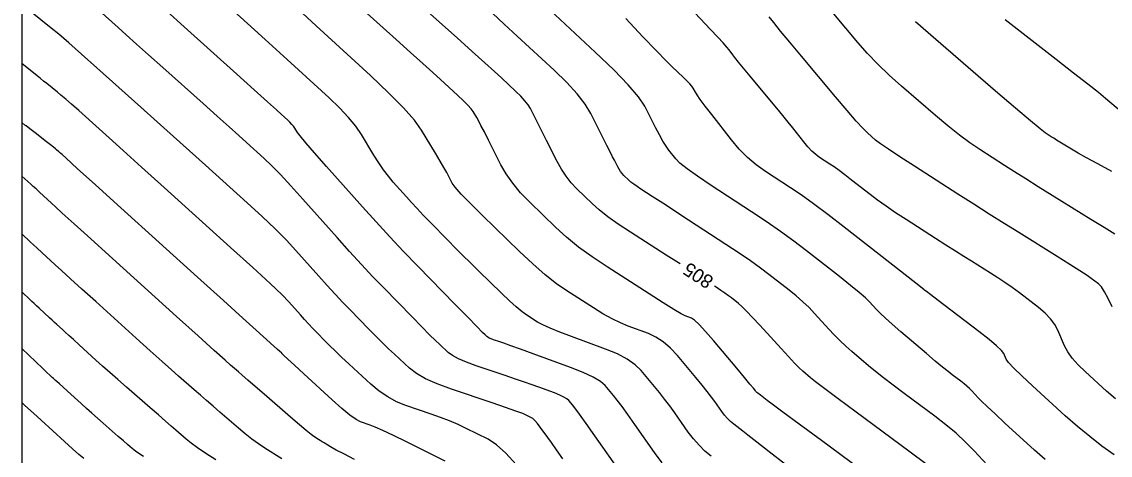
# Model space of a CAD drawing. Extents: x 2082232 to 2083549, y 592624 to 593832.
# Drawn here: x 2082231.8 to 2082287.6, y 593361.9 to 593384.1 of the extents above; entities that cross this region are included whole.
import ezdxf

# ---------------------------------------------------------------- set-up
doc = ezdxf.new("R2010")
doc.units = 0
for name, color, linetype in [('DT_X_Contour_Major', 7, 'Continuous'), ('DT_X_Contour_Minor', 7, 'Continuous'), ('DT_X_TIN_Hull', 7, 'Continuous')]:
    doc.layers.add(name, color=color, linetype=linetype)

msp = doc.modelspace()

# ---------------------------------------------------------------- linework, layer by layer
at = {"layer": 'DT_X_Contour_Major'}
for points in [[(2082265.562, 593371.67), (2082265.476, 593371.724), (2082264.846, 593372.128), (2082263.024, 593373.296), (2082262.389, 593373.715), (2082261.85, 593374.098), (2082261.407, 593374.445), (2082261.06, 593374.754), (2082260.262, 593375.531), (2082259.975, 593375.837), (2082259.712, 593376.171), (2082259.472, 593376.533), (2082259.257, 593376.924), (2082258.714, 593378.004), (2082258.525, 593378.381), (2082258.363, 593378.702), (2082258.23, 593378.966), (2082258.124, 593379.174), (2082257.88, 593379.654), (2082257.765, 593379.844), (2082257.603, 593380.054), (2082257.394, 593380.284), (2082257.137, 593380.533), (2082256.391, 593381.226), (2082256.038, 593381.549), (2082255.542, 593381.999), (2082254.902, 593382.577), (2082254.117, 593383.283), (2082251.833, 593385.333)], [(2082262.531, 593360.934), (2082261.185, 593362.846), (2082260.735, 593363.484), (2082260.393, 593363.963), (2082260.161, 593364.283), (2082260.039, 593364.444), (2082259.857, 593364.662), (2082259.759, 593364.747), (2082259.603, 593364.84), (2082259.388, 593364.94), (2082259.115, 593365.047), (2082258.309, 593365.342), (2082257.975, 593365.463), (2082257.577, 593365.603), (2082257.116, 593365.763), (2082256.592, 593365.942), (2082255.107, 593366.447), (2082254.6, 593366.632), (2082254.191, 593366.807), (2082253.88, 593366.972), (2082253.667, 593367.129), (2082253.23, 593367.533), (2082253.018, 593367.735), (2082252.712, 593368.039), (2082252.311, 593368.444), (2082251.814, 593368.951), (2082250.364, 593370.438), (2082249.806, 593371.018), (2082249.22, 593371.644), (2082248.605, 593372.314), (2082247.962, 593373.03), (2082246.21, 593375.001), (2082245.593, 593375.685), (2082245.055, 593376.262), (2082244.597, 593376.73), (2082244.219, 593377.089), (2082243.317, 593377.904), (2082242.924, 593378.258), (2082242.422, 593378.71), (2082241.81, 593379.258), (2082241.089, 593379.904), (2082239.019, 593381.755), (2082238.295, 593382.404), (2082237.672, 593382.962), (2082237.151, 593383.429), (2082236.733, 593383.805), (2082235.753, 593384.687)], [(2082287.724, 593369.463), (2082287.525, 593369.901), (2082287.342, 593370.244), (2082287.176, 593370.493), (2082287.027, 593370.647), (2082286.653, 593370.933), (2082286.438, 593371.083), (2082286.074, 593371.321), (2082285.562, 593371.647), (2082284.902, 593372.06), (2082282.942, 593373.278), (2082282.195, 593373.744), (2082281.423, 593374.23), (2082280.626, 593374.736), (2082279.804, 593375.261), (2082277.58, 593376.688), (2082276.831, 593377.174), (2082276.25, 593377.56), (2082275.838, 593377.846), (2082275.594, 593378.033), (2082275.17, 593378.399), (2082274.948, 593378.618), (2082274.602, 593378.998), (2082274.131, 593379.541), (2082273.536, 593380.245), (2082271.782, 593382.34), (2082271.185, 593383.055), (2082270.713, 593383.63), (2082270.363, 593384.065), (2082270.137, 593384.36)], [(2082245.123, 593361.668), (2082244.259, 593362.213), (2082243.932, 593362.431), (2082243.596, 593362.675), (2082243.253, 593362.944), (2082242.902, 593363.239), (2082241.955, 593364.062), (2082241.607, 593364.365), (2082241.271, 593364.657), (2082240.948, 593364.938), (2082240.638, 593365.209), (2082239.828, 593365.917), (2082239.465, 593366.237), (2082238.983, 593366.668), (2082238.382, 593367.207), (2082237.662, 593367.857), (2082235.584, 593369.736), (2082234.87, 593370.383), (2082234.285, 593370.913), (2082233.831, 593371.327), (2082233.506, 593371.625), (2082232.814, 593372.265), (2082232.578, 593372.483), (2082232.387, 593372.66), (2082232.242, 593372.794), (2082231.787, 593373.214)], [(2082278.233, 593361.362), (2082277.298, 593362.067), (2082274.587, 593364.067), (2082273.679, 593364.739), (2082272.988, 593365.256), (2082272.513, 593365.618), (2082272.255, 593365.824), (2082271.855, 593366.167), (2082271.673, 593366.335), (2082271.426, 593366.584), (2082271.115, 593366.914), (2082270.74, 593367.323), (2082269.652, 593368.522), (2082269.278, 593368.929), (2082268.971, 593369.251), (2082268.732, 593369.486), (2082268.561, 593369.637), (2082268.194, 593369.924), (2082268.041, 593370.039), (2082267.86, 593370.169), (2082267.648, 593370.313), (2082267.407, 593370.473), (2082267.324, 593370.527)]]:
    msp.add_lwpolyline(points, dxfattribs=at)
at = {"layer": 'DT_X_Contour_Minor'}
for points in [[(2082284.287, 593361.63), (2082283.747, 593362.114), (2082282.23, 593363.502), (2082281.718, 593363.973), (2082281.318, 593364.347), (2082281.031, 593364.622), (2082280.857, 593364.8), (2082280.541, 593365.143), (2082280.417, 593365.271), (2082280.279, 593365.398), (2082280.129, 593365.524), (2082279.967, 593365.65), (2082279.516, 593365.982), (2082279.307, 593366.144), (2082279.018, 593366.379), (2082278.648, 593366.688), (2082278.199, 593367.071), (2082276.894, 593368.191), (2082276.449, 593368.577), (2082276.092, 593368.896), (2082275.823, 593369.148), (2082275.642, 593369.332), (2082275.278, 593369.733), (2082275.079, 593369.927), (2082274.756, 593370.207), (2082274.309, 593370.573), (2082273.737, 593371.026), (2082272.046, 593372.349), (2082271.394, 593372.846), (2082270.706, 593373.346), (2082269.983, 593373.849), (2082269.224, 593374.355), (2082267.154, 593375.707), (2082266.458, 593376.172), (2082265.923, 593376.553), (2082265.549, 593376.849), (2082265.336, 593377.062), (2082264.982, 593377.517), (2082264.84, 593377.718), (2082264.679, 593377.977), (2082264.499, 593378.297), (2082264.301, 593378.676), (2082263.747, 593379.765), (2082263.433, 593380.246), (2082262.905, 593380.87), (2082262.164, 593381.638), (2082261.21, 593382.55), (2082258.38, 593385.173)], [(2082259.553, 593361.66), (2082259.218, 593362.135), (2082258.957, 593362.501), (2082258.773, 593362.758), (2082258.381, 593363.299), (2082258.241, 593363.482), (2082258.115, 593363.626), (2082258.003, 593363.73), (2082257.906, 593363.795), (2082257.663, 593363.914), (2082257.485, 593363.987), (2082257.135, 593364.115), (2082256.611, 593364.298), (2082255.915, 593364.537), (2082253.827, 593365.247), (2082253.105, 593365.514), (2082252.507, 593365.781), (2082252.032, 593366.049), (2082251.68, 593366.317), (2082250.906, 593367.033), (2082250.607, 593367.315), (2082250.289, 593367.622), (2082249.953, 593367.956), (2082249.599, 593368.316), (2082248.629, 593369.31), (2082248.256, 593369.698), (2082247.864, 593370.116), (2082247.453, 593370.564), (2082247.023, 593371.043), (2082245.851, 593372.361), (2082245.366, 593372.884), (2082244.789, 593373.466), (2082244.12, 593374.107), (2082243.359, 593374.806), (2082241.208, 593376.749), (2082240.396, 593377.482), (2082239.574, 593378.222), (2082238.741, 593378.969), (2082237.899, 593379.724), (2082235.637, 593381.747), (2082234.855, 593382.444), (2082234.204, 593383.015), (2082233.685, 593383.461), (2082233.297, 593383.783), (2082231.787, 593384.998)], [(2082264.65, 593361.466), (2082264.256, 593361.988), (2082263.236, 593363.436), (2082262.882, 593363.935), (2082262.582, 593364.348), (2082262.336, 593364.673), (2082262.146, 593364.912), (2082261.712, 593365.431), (2082261.479, 593365.635), (2082261.107, 593365.856), (2082260.595, 593366.094), (2082259.943, 593366.349), (2082258.019, 593367.054), (2082257.372, 593367.291), (2082256.873, 593367.472), (2082256.523, 593367.598), (2082256.322, 593367.669), (2082255.983, 593367.784), (2082255.867, 593367.827), (2082255.773, 593367.867), (2082255.702, 593367.905), (2082255.653, 593367.94), (2082255.553, 593368.033), (2082255.43, 593368.156), (2082255.135, 593368.456), (2082254.668, 593368.933), (2082254.03, 593369.587), (2082252.099, 593371.566), (2082251.379, 593372.313), (2082250.667, 593373.069), (2082249.963, 593373.833), (2082249.267, 593374.607), (2082247.42, 593376.683), (2082246.808, 593377.375), (2082246.356, 593377.894), (2082246.063, 593378.241), (2082245.93, 593378.415), (2082245.79, 593378.647), (2082245.728, 593378.738), (2082245.647, 593378.837), (2082245.548, 593378.943), (2082245.43, 593379.056), (2082245.091, 593379.368), (2082244.853, 593379.583), (2082244.395, 593379.997), (2082243.717, 593380.609), (2082242.818, 593381.419), (2082240.127, 593383.842), (2082239.22, 593384.666)], [(2082267.148, 593361.8), (2082266.832, 593362.067), (2082266.532, 593362.362), (2082266.248, 593362.687), (2082265.98, 593363.042), (2082265.288, 593364.025), (2082265.028, 593364.387), (2082264.77, 593364.733), (2082264.511, 593365.064), (2082264.254, 593365.379), (2082263.567, 593366.201), (2082263.259, 593366.5), (2082262.852, 593366.783), (2082262.345, 593367.049), (2082261.738, 593367.298), (2082259.987, 593367.939), (2082259.386, 593368.166), (2082258.897, 593368.367), (2082258.519, 593368.542), (2082258.253, 593368.69), (2082257.692, 593369.049), (2082257.453, 593369.221), (2082257.158, 593369.464), (2082256.806, 593369.781), (2082256.397, 593370.17), (2082255.233, 593371.305), (2082254.807, 593371.722), (2082254.402, 593372.123), (2082254.02, 593372.507), (2082253.659, 593372.874), (2082252.726, 593373.831), (2082252.388, 593374.18), (2082252.074, 593374.511), (2082251.785, 593374.823), (2082251.52, 593375.117), (2082250.845, 593375.876), (2082250.594, 593376.175), (2082250.345, 593376.503), (2082250.098, 593376.861), (2082249.855, 593377.248), (2082249.209, 593378.319), (2082248.923, 593378.738), (2082248.552, 593379.191), (2082248.096, 593379.678), (2082247.553, 593380.198), (2082245.992, 593381.632), (2082245.411, 593382.164), (2082244.842, 593382.684), (2082244.282, 593383.191), (2082243.734, 593383.686), (2082242.285, 593384.991)], [(2082270.969, 593361.375), (2082270.138, 593362.023), (2082269.497, 593362.525), (2082269.043, 593362.879), (2082268.778, 593363.086), (2082268.321, 593363.44), (2082268.155, 593363.581), (2082267.996, 593363.737), (2082267.846, 593363.909), (2082267.705, 593364.096), (2082267.339, 593364.615), (2082267.175, 593364.838), (2082266.958, 593365.118), (2082266.686, 593365.454), (2082266.361, 593365.847), (2082265.422, 593366.97), (2082265.065, 593367.356), (2082264.7, 593367.673), (2082264.325, 593367.92), (2082263.941, 593368.097), (2082262.906, 593368.476), (2082262.503, 593368.641), (2082262.069, 593368.852), (2082261.605, 593369.11), (2082261.111, 593369.413), (2082259.752, 593370.284), (2082259.218, 593370.655), (2082258.634, 593371.118), (2082258.001, 593371.671), (2082257.318, 593372.316), (2082255.431, 593374.155), (2082254.803, 593374.775), (2082254.334, 593375.259), (2082254.025, 593375.605), (2082253.875, 593375.814), (2082253.687, 593376.188), (2082253.592, 593376.366), (2082253.447, 593376.62), (2082253.254, 593376.949), (2082253.011, 593377.355), (2082252.298, 593378.537), (2082251.934, 593379.045), (2082251.375, 593379.681), (2082250.623, 593380.447), (2082249.676, 593381.341), (2082246.892, 593383.897), (2082245.969, 593384.745)], [(2082276.26, 593360.057), (2082272.814, 593362.6), (2082271.671, 593363.444), (2082270.826, 593364.068), (2082270.281, 593364.473), (2082270.034, 593364.659), (2082269.686, 593364.931), (2082269.618, 593364.984), (2082269.571, 593365.021), (2082269.543, 593365.043), (2082269.494, 593365.08), (2082269.477, 593365.095), (2082269.46, 593365.112), (2082269.444, 593365.13), (2082269.429, 593365.15), (2082269.391, 593365.204), (2082269.322, 593365.289), (2082269.146, 593365.502), (2082268.861, 593365.844), (2082268.469, 593366.314), (2082267.277, 593367.739), (2082266.871, 593368.212), (2082266.547, 593368.563), (2082266.305, 593368.79), (2082266.144, 593368.896), (2082265.825, 593369.013), (2082265.619, 593369.116), (2082265.241, 593369.337), (2082264.691, 593369.678), (2082263.968, 593370.136), (2082261.812, 593371.518), (2082261.042, 593372.032), (2082260.348, 593372.54), (2082259.73, 593373.041), (2082259.189, 593373.535), (2082257.846, 593374.843), (2082257.376, 593375.331), (2082256.973, 593375.814), (2082256.637, 593376.292), (2082256.367, 593376.765), (2082255.736, 593378.021), (2082255.52, 593378.447), (2082255.346, 593378.784), (2082255.215, 593379.032), (2082255.125, 593379.191), (2082254.941, 593379.496), (2082254.839, 593379.633), (2082254.673, 593379.818), (2082254.441, 593380.05), (2082254.144, 593380.33), (2082253.265, 593381.137), (2082252.875, 593381.492), (2082252.366, 593381.954), (2082251.738, 593382.52), (2082250.99, 593383.193), (2082248.835, 593385.126)], [(2082287.902, 593364.742), (2082287.446, 593365.136), (2082286.359, 593366.131), (2082285.986, 593366.495), (2082285.683, 593366.84), (2082285.45, 593367.167), (2082285.287, 593367.475), (2082284.946, 593368.272), (2082284.788, 593368.568), (2082284.57, 593368.86), (2082284.291, 593369.148), (2082283.952, 593369.431), (2082282.966, 593370.181), (2082282.597, 593370.455), (2082282.229, 593370.716), (2082281.862, 593370.964), (2082281.495, 593371.199), (2082280.518, 593371.806), (2082280.127, 593372.05), (2082279.686, 593372.328), (2082279.197, 593372.64), (2082278.658, 593372.985), (2082277.154, 593373.949), (2082276.616, 593374.301), (2082276.13, 593374.632), (2082275.694, 593374.943), (2082275.31, 593375.233), (2082274.353, 593375.981), (2082274.015, 593376.243), (2082273.717, 593376.466), (2082273.46, 593376.652), (2082273.243, 593376.799), (2082272.718, 593377.142), (2082272.519, 593377.288), (2082272.317, 593377.47), (2082272.112, 593377.687), (2082271.903, 593377.94), (2082271.342, 593378.662), (2082271.111, 593378.955), (2082270.837, 593379.293), (2082270.522, 593379.677), (2082270.165, 593380.105), (2082269.158, 593381.308), (2082268.819, 593381.715), (2082268.556, 593382.033), (2082268.371, 593382.262), (2082268.262, 593382.403), (2082268.074, 593382.659), (2082267.962, 593382.797), (2082267.767, 593383.017), (2082267.49, 593383.319), (2082267.13, 593383.703), (2082266.06, 593384.838)], [(2082281.754, 593360.878), (2082280.648, 593362.081), (2082280.211, 593362.53), (2082279.729, 593362.977), (2082279.203, 593363.419), (2082278.632, 593363.858), (2082277.052, 593365.024), (2082276.493, 593365.441), (2082276.003, 593365.818), (2082275.581, 593366.153), (2082275.227, 593366.448), (2082274.375, 593367.179), (2082274.061, 593367.456), (2082273.759, 593367.74), (2082273.469, 593368.031), (2082273.191, 593368.328), (2082272.465, 593369.128), (2082272.178, 593369.428), (2082271.864, 593369.729), (2082271.52, 593370.03), (2082271.149, 593370.331), (2082270.12, 593371.136), (2082269.692, 593371.459), (2082269.182, 593371.823), (2082268.589, 593372.229), (2082267.913, 593372.677), (2082265.999, 593373.927), (2082265.344, 593374.354), (2082264.814, 593374.699), (2082264.409, 593374.962), (2082264.13, 593375.142), (2082263.553, 593375.512), (2082263.352, 593375.644), (2082263.181, 593375.766), (2082263.041, 593375.875), (2082262.931, 593375.974), (2082262.678, 593376.22), (2082262.587, 593376.317), (2082262.504, 593376.422), (2082262.428, 593376.537), (2082262.36, 593376.661), (2082262.188, 593377.003), (2082262.102, 593377.173), (2082261.975, 593377.424), (2082261.806, 593377.757), (2082261.595, 593378.171), (2082260.978, 593379.387), (2082260.687, 593379.868), (2082260.276, 593380.399), (2082259.746, 593380.981), (2082259.096, 593381.613), (2082257.205, 593383.367), (2082256.532, 593383.989), (2082255.933, 593384.539)], [(2082287.834, 593361.878), (2082287.204, 593362.323), (2082286.575, 593362.805), (2082285.946, 593363.323), (2082285.319, 593363.879), (2082283.647, 593365.409), (2082283.092, 593365.925), (2082282.682, 593366.326), (2082282.417, 593366.611), (2082282.297, 593366.781), (2082282.169, 593367.08), (2082282.053, 593367.235), (2082281.801, 593367.474), (2082281.413, 593367.797), (2082280.89, 593368.205), (2082278.795, 593369.799), (2082278.423, 593370.082), (2082278.198, 593370.254), (2082278.119, 593370.314), (2082278.101, 593370.33), (2082278.095, 593370.335), (2082278.093, 593370.336), (2082278.091, 593370.339), (2082277.98, 593370.426), (2082277.649, 593370.685), (2082276.325, 593371.721), (2082273.972, 593373.561), (2082273.139, 593374.205), (2082272.405, 593374.755), (2082271.77, 593375.213), (2082271.234, 593375.577), (2082269.936, 593376.424), (2082269.463, 593376.764), (2082269.016, 593377.145), (2082268.596, 593377.57), (2082268.202, 593378.038), (2082267.188, 593379.341), (2082266.851, 593379.779), (2082266.597, 593380.115), (2082266.429, 593380.35), (2082266.345, 593380.483), (2082266.233, 593380.702), (2082266.17, 593380.799), (2082266.064, 593380.924), (2082265.915, 593381.079), (2082265.723, 593381.262), (2082265.154, 593381.79), (2082264.845, 593382.093), (2082264.345, 593382.607), (2082263.654, 593383.332), (2082262.772, 593384.268)], [(2082287.871, 593373.203), (2082287.32, 593373.538), (2082286.64, 593373.958), (2082284.651, 593375.194), (2082283.939, 593375.638), (2082283.294, 593376.042), (2082282.716, 593376.407), (2082282.206, 593376.733), (2082280.934, 593377.549), (2082280.434, 593377.888), (2082279.891, 593378.291), (2082279.302, 593378.759), (2082278.67, 593379.292), (2082276.923, 593380.798), (2082276.292, 593381.362), (2082275.709, 593381.922), (2082275.175, 593382.479), (2082274.688, 593383.033), (2082273.454, 593384.506)], [(2082287.718, 593376.411), (2082286.986, 593376.803), (2082286.41, 593377.116), (2082285.989, 593377.351), (2082285.723, 593377.507), (2082285.223, 593377.818), (2082285.043, 593377.929), (2082284.881, 593378.031), (2082284.736, 593378.123), (2082284.607, 593378.205), (2082284.287, 593378.411), (2082284.038, 593378.602), (2082283.531, 593379.022), (2082282.767, 593379.672), (2082281.745, 593380.55), (2082278.677, 593383.197), (2082277.636, 593384.106)], [(2082288.161, 593379.514), (2082287.394, 593380.161), (2082287.019, 593380.469), (2082286.472, 593380.907), (2082285.751, 593381.474), (2082284.857, 593382.171), (2082282.242, 593384.202)], [(2082257.151, 593361.373), (2082256.627, 593361.958), (2082256.145, 593362.392), (2082255.707, 593362.674), (2082254.593, 593363.223), (2082254.168, 593363.424), (2082253.725, 593363.615), (2082253.265, 593363.795), (2082252.789, 593363.965), (2082251.496, 593364.405), (2082251.02, 593364.597), (2082250.561, 593364.845), (2082250.119, 593365.148), (2082249.694, 593365.506), (2082248.583, 593366.533), (2082248.195, 593366.894), (2082247.866, 593367.205), (2082247.595, 593367.468), (2082247.383, 593367.68), (2082246.894, 593368.182), (2082246.705, 593368.377), (2082246.508, 593368.588), (2082246.3, 593368.815), (2082246.084, 593369.056), (2082245.493, 593369.721), (2082245.139, 593370.083), (2082244.523, 593370.67), (2082243.643, 593371.484), (2082242.499, 593372.523), (2082239.099, 593375.594), (2082237.934, 593376.646), (2082236.989, 593377.499), (2082236.264, 593378.151), (2082235.76, 593378.604), (2082234.707, 593379.545), (2082234.343, 593379.869), (2082234.04, 593380.135), (2082233.799, 593380.343), (2082233.619, 593380.492), (2082233.067, 593380.936), (2082232.91, 593381.063), (2082232.748, 593381.193), (2082232.58, 593381.328), (2082231.787, 593381.966)], [(2082253.508, 593361.553), (2082251.524, 593362.532), (2082250.85, 593362.861), (2082250.315, 593363.115), (2082249.919, 593363.292), (2082249.663, 593363.393), (2082249.166, 593363.562), (2082248.935, 593363.681), (2082248.615, 593363.909), (2082248.206, 593364.246), (2082247.707, 593364.694), (2082246.259, 593366.033), (2082245.784, 593366.473), (2082245.443, 593366.789), (2082245.238, 593366.979), (2082245.167, 593367.045), (2082245.159, 593367.054), (2082245.155, 593367.057), (2082245.152, 593367.061), (2082245.148, 593367.065), (2082245.144, 593367.069), (2082245.134, 593367.081), (2082245.105, 593367.107), (2082245.026, 593367.179), (2082244.897, 593367.296), (2082244.718, 593367.458), (2082244.174, 593367.949), (2082243.811, 593368.278), (2082243.129, 593368.894), (2082242.128, 593369.799), (2082240.808, 593370.993), (2082236.864, 593374.559), (2082235.567, 593375.733), (2082234.633, 593376.577), (2082234.062, 593377.094), (2082233.854, 593377.282), (2082233.785, 593377.346), (2082233.758, 593377.371), (2082233.729, 593377.397), (2082233.698, 593377.424), (2082233.666, 593377.453), (2082233.576, 593377.531), (2082233.519, 593377.579), (2082233.414, 593377.662), (2082233.262, 593377.782), (2082233.062, 593377.937), (2082232.467, 593378.4), (2082232.267, 593378.556), (2082232.114, 593378.675), (2082232.009, 593378.757), (2082231.95, 593378.804), (2082231.787, 593378.935)], [(2082248.864, 593361.64), (2082248.306, 593361.92), (2082247.924, 593362.116), (2082247.72, 593362.228), (2082247.412, 593362.413), (2082247.3, 593362.48), (2082247.194, 593362.544), (2082247.096, 593362.605), (2082247.004, 593362.663), (2082246.769, 593362.812), (2082246.628, 593362.916), (2082246.382, 593363.116), (2082246.031, 593363.413), (2082245.576, 593363.806), (2082244.22, 593364.984), (2082243.757, 593365.386), (2082243.383, 593365.711), (2082243.098, 593365.959), (2082242.903, 593366.13), (2082242.502, 593366.48), (2082242.216, 593366.735), (2082241.658, 593367.236), (2082240.83, 593367.983), (2082239.73, 593368.977), (2082236.436, 593371.956), (2082235.327, 593372.959), (2082234.47, 593373.736), (2082233.866, 593374.285), (2082233.513, 593374.608), (2082232.91, 593375.165), (2082232.7, 593375.359), (2082232.521, 593375.523), (2082232.373, 593375.656), (2082232.257, 593375.759), (2082231.787, 593376.17)], [(2082241.75, 593361.615), (2082241.236, 593361.946), (2082240.81, 593362.233), (2082240.475, 593362.475), (2082240.228, 593362.673), (2082239.691, 593363.14), (2082239.457, 593363.343), (2082239.16, 593363.602), (2082238.798, 593363.918), (2082238.373, 593364.289), (2082237.154, 593365.354), (2082236.714, 593365.74), (2082236.307, 593366.099), (2082235.934, 593366.431), (2082235.594, 593366.737), (2082234.732, 593367.517), (2082234.436, 593367.785), (2082234.193, 593368.005), (2082234.005, 593368.177), (2082233.87, 593368.3), (2082233.583, 593368.565), (2082233.471, 593368.669), (2082233.349, 593368.782), (2082233.217, 593368.903), (2082232.687, 593369.393), (2082232.548, 593369.522), (2082232.423, 593369.638), (2082232.311, 593369.743), (2082232.213, 593369.837), (2082231.787, 593370.243)], [(2082238.025, 593361.792), (2082237.696, 593362.006), (2082237.555, 593362.106), (2082237.426, 593362.218), (2082237.346, 593362.287), (2082237.206, 593362.409), (2082237.004, 593362.586), (2082236.74, 593362.816), (2082235.955, 593363.502), (2082235.665, 593363.757), (2082235.382, 593364.008), (2082235.106, 593364.256), (2082234.838, 593364.499), (2082234.134, 593365.142), (2082233.897, 593365.358), (2082233.716, 593365.522), (2082233.591, 593365.635), (2082233.521, 593365.696), (2082233.408, 593365.79), (2082233.343, 593365.849), (2082233.23, 593365.954), (2082233.07, 593366.105), (2082232.863, 593366.301), (2082231.787, 593367.328)], [(2082234.969, 593361.676), (2082234.716, 593361.891), (2082234.385, 593362.184), (2082233.976, 593362.555), (2082232.781, 593363.647), (2082232.387, 593364.006), (2082232.103, 593364.266), (2082231.928, 593364.426), (2082231.863, 593364.485), (2082231.833, 593364.512), (2082231.823, 593364.521), (2082231.815, 593364.528), (2082231.809, 593364.534), (2082231.804, 593364.538), (2082231.787, 593364.553)]]:
    msp.add_lwpolyline(points, dxfattribs=at)
at = {"layer": 'DT_X_TIN_Hull'}
msp.add_lwpolyline([(2082231.787, 593385.022), (2082231.787, 593378.886), (2082231.787, 593377.418), (2082231.787, 593374.63), (2082231.787, 593370.97), (2082231.787, 593365.705), (2082231.787, 593364.517), (2082231.787, 593361.416), (2082231.787, 593357.443), (2082231.787, 593353.951), (2082231.787, 593351.16), (2082231.787, 593348.211), (2082231.787, 593338.224), (2082231.787, 593335.312), (2082231.787, 593331.142), (2082231.787, 593329.814), (2082231.787, 593322.524), (2082231.787, 593319.977)], dxfattribs=at)

# ---------------------------------------------------------------- texts
at = {"layer": 'DT_X_Contour_Major'}
msp.add_text('805', height=0.7, rotation=147.0507, dxfattribs=at).set_placement((2082267.331, 593370.943))

doc.saveas('drawing.dxf')
